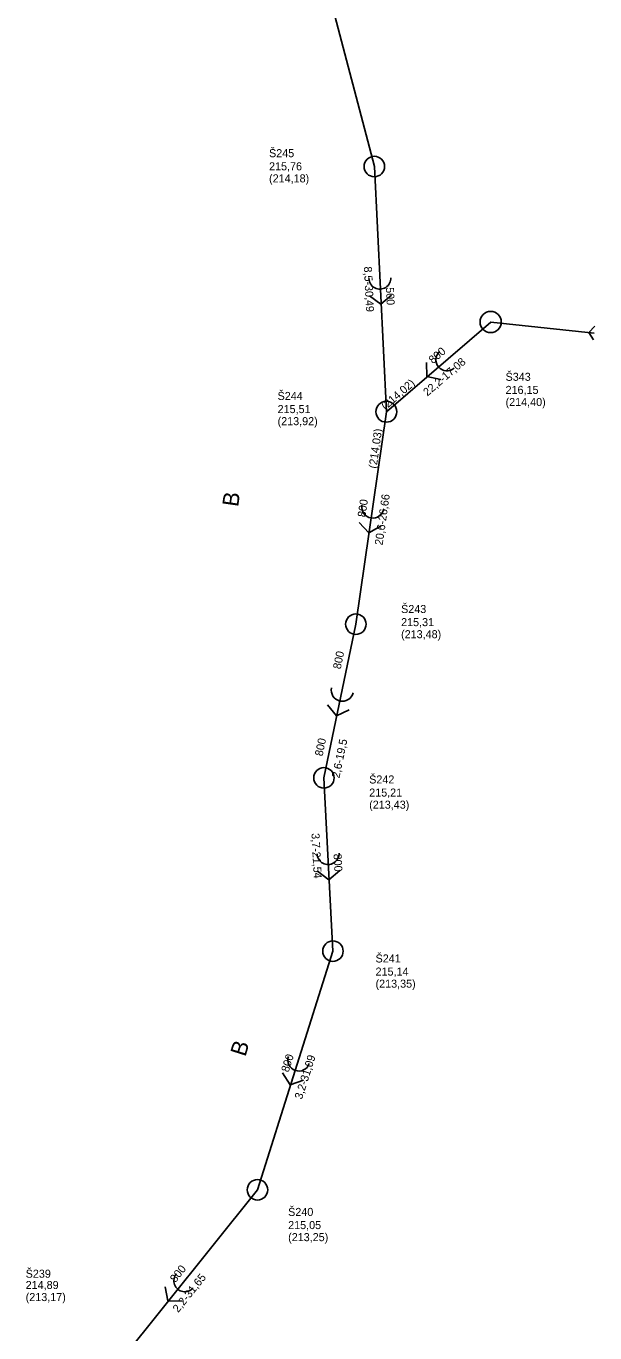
# Model space of a CAD drawing. Extents: x -569540 to -569072, y -1179643 to -1178245.
# Drawn here: x -569142.4 to -569071.8, y -1178576.3 to -1178414 of the extents above; entities that cross this region are included whole.
import ezdxf

# ---------------------------------------------------------------- set-up
doc = ezdxf.new("R2010")
doc.units = 0
for name, color, linetype in [('Vrstva 1', 7, 'Continuous'), ('Vrstva 15', 7, 'Continuous'), ('Vrstva 29', 7, 'Continuous'), ('Vrstva 35', 7, 'Continuous'), ('Vrstva 41', 7, 'Continuous'), ('Vrstva 44', 7, 'Continuous'), ('Vrstva 45', 7, 'Continuous'), ('Vrstva 56', 7, 'Continuous'), ('Vrstva 57', 7, 'Continuous')]:
    doc.layers.add(name, color=color, linetype=linetype)

# ---------------------------------------------------------------- blocks, each defined once
blk = doc.blocks.new('100')
at = {"layer": 'Vrstva 1'}
blk.add_circle((0, 0), 1.27, dxfattribs=at)
blk = doc.blocks.new('86')
at = {"layer": 'Vrstva 1'}
blk.add_lwpolyline([(0.79, 1.37), (1.89, 0), (0.79, -1.38)], dxfattribs=at)
blk.add_arc((-1.37, 0), 1.37, 270, 90, dxfattribs=at)
blk = doc.blocks.new('91')
at = {"layer": 'Vrstva 1'}
blk.add_lwpolyline([(0.79, 1.37), (1.89, 0), (0.79, -1.38)], dxfattribs=at)
blk.add_arc((-1.37, 0), 1.37, 270, 90, dxfattribs=at)

msp = doc.modelspace()

# ---------------------------------------------------------------- linework, layer by layer
at = {"layer": 'Vrstva 15'}
for p, q in [((-569111.13, -1178385.58), (-569099.16, -1178431.42)), ((-569099.16, -1178431.42), (-569097.67, -1178461.87)), ((-569084.72, -1178450.73), (-569097.67, -1178461.87)), ((-569071.87, -1178452.1), (-569084.72, -1178450.73)), ((-569097.67, -1178461.87), (-569101.45, -1178488.26)), ((-569101.45, -1178488.26), (-569105.42, -1178507.34)), ((-569105.42, -1178507.34), (-569104.3, -1178528.86)), ((-569104.3, -1178528.86), (-569113.67, -1178558.5)), ((-569113.67, -1178558.5), (-569133.46, -1178583.19))]:
    msp.add_line(p, q, dxfattribs=at)
at = {"layer": 'Vrstva 41'}
msp.add_lwpolyline([(-569071.96, -1178452.95), (-569072.55, -1178452.01), (-569071.79, -1178451.25)], dxfattribs=at)

# ---------------------------------------------------------------- block references
at = {"layer": 'Vrstva 29'}
for p, xscale, yscale, rotation in [((-569099.16, -1178431.42), 0.9999999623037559, 0.999999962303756, 99.00000013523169), ((-569084.72, -1178450.73), 1.0365458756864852, 1.0365458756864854, -158.02850914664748), ((-569097.67, -1178461.87), 1.022584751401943, 1.022584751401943, 154.18102569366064), ((-569101.45, -1178488.26), 0.9999999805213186, 0.9999999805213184, -100.99999941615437), ((-569105.42, -1178507.34), 0.9999999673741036, 0.9999999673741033, 86.00000004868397), ((-569104.3, -1178528.86), 0.9999999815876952, 0.9999999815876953, -97.99999954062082), ((-569113.67, -1178558.5), 0.999999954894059, 0.9999999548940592, -119.00000058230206)]:
    msp.add_blockref('100', p, dxfattribs=dict(at, xscale=xscale, yscale=yscale, rotation=rotation))
at = {"layer": 'Vrstva 41'}
for name, p, xscale, yscale, rotation in [('91', (-569098.42, -1178446.64), 0.9999999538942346, 0.9999999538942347, -87.9999999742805), ('86', (-569091.2, -1178456.3), 0.9999999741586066, 0.9999999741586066, -140.00000129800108), ('86', (-569099.56, -1178475.06), 0.9999999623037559, 0.999999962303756, -99.00000013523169), ('86', (-569103.44, -1178497.8), 0.9999999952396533, 0.9999999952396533, -102.9999994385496), ('86', (-569104.86, -1178518.1), 0.9999999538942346, 0.9999999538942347, -87.9999999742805), ('86', (-569108.98, -1178543.68), 0.9999999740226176, 0.9999999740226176, -108.99999960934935), ('86', (-569123.56, -1178570.85), 0.9999999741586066, 0.9999999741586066, -129.99999870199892)]:
    msp.add_blockref(name, p, dxfattribs=dict(at, xscale=xscale, yscale=yscale, rotation=rotation))

# ---------------------------------------------------------------- texts
at = {"layer": 'Vrstva 35'}
for rotation, p in [(81.86, (-569116.07, -1178473.75)), (72.46, (-569115.18, -1178542.05))]:
    msp.add_text('B', height=2, rotation=rotation, dxfattribs=at).set_placement(p)
at = {"layer": 'Vrstva 44'}
for s, rotation, p in [('500', 272.8, (-569097.73, -1178446.43)), ('800', 40.69, (-569091.89, -1178455.97)), ('800', 81.86, (-569100.26, -1178475.02)), ('800', 78.23, (-569103.34, -1178493.9)), ('800', 78.23, (-569105.59, -1178504.71)), ('800', 273, (-569104.23, -1178516.78)), ('800', 72.46, (-569109.81, -1178543.97)), ('800', 51.28, (-569123.85, -1178570.09))]:
    msp.add_text(s, height=1, rotation=rotation, dxfattribs=at).set_placement(p)
at = {"layer": 'Vrstva 45'}
for s, rotation, p in [('8,5-30,49', 272.8, (-569100.46, -1178443.86)), ('22,2-17,08', 40.69, (-569092.57, -1178459.99)), ('(214,02)', 40.69, (-569097.8, -1178461.72)), ('(214,03)', 81.86, (-569098.89, -1178468.97)), ('20,6-26,66', 81.86, (-569098.14, -1178478.5)), ('2,6-19,5', 78.23, (-569103.5, -1178507.43)), ('3,7-21,54', 273, (-569106.97, -1178514.23)), ('3,2-31,09', 72.46, (-569108.14, -1178547.33)), ('2,2-31,65', 51.28, (-569123.51, -1178573.82))]:
    msp.add_text(s, height=1, rotation=rotation, dxfattribs=at).set_placement(p)
at = {"layer": 'Vrstva 56'}
for s, p in [('215,76 ', (-569112.23, -1178431.89)), ('(214,18)', (-569112.23, -1178433.39)), ('216,15 ', (-569082.87, -1178459.66)), ('(214,40)', (-569082.87, -1178461.16)), ('215,51 ', (-569111.17, -1178462.04)), ('(213,92)', (-569111.17, -1178463.54)), ('215,31 ', (-569095.84, -1178488.5)), ('(213,48)', (-569095.84, -1178490)), ('215,21 ', (-569099.8, -1178509.67)), ('(213,43)', (-569099.8, -1178511.17)), ('215,14 ', (-569099.01, -1178531.9)), ('(213,35)', (-569099.01, -1178533.4)), ('215,05 ', (-569109.86, -1178563.38)), ('(213,25)', (-569109.86, -1178564.88)), ('214,89 ', (-569142.44, -1178570.82)), ('(213,17)', (-569142.44, -1178572.32))]:
    msp.add_text(s, height=1, dxfattribs=at).set_placement(p)
at = {"layer": 'Vrstva 57'}
for s, p in [('Š245', (-569112.23, -1178430.26)), ('Š343', (-569082.87, -1178458.03)), ('Š244', (-569111.17, -1178460.41)), ('Š243', (-569095.84, -1178486.87)), ('Š242', (-569099.8, -1178508.04)), ('Š241', (-569099.01, -1178530.27)), ('Š240', (-569109.86, -1178561.75)), ('Š239', (-569142.44, -1178569.42))]:
    msp.add_text(s, height=1, dxfattribs=at).set_placement(p)

doc.saveas('drawing.dxf')
